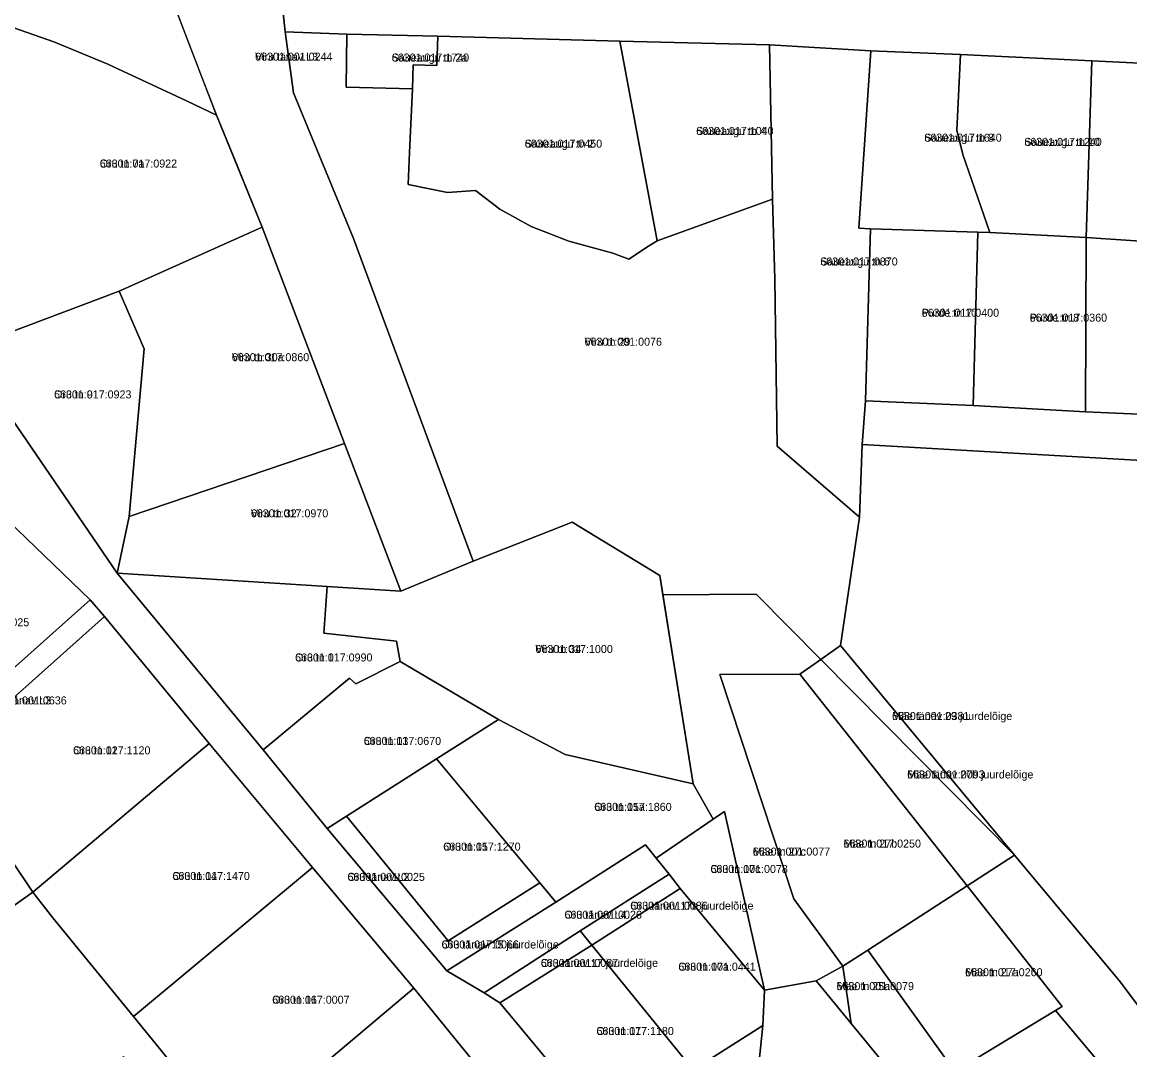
# Model space of a CAD drawing. Extents: x 632278 to 636344, y 6578401 to 6583362.
# Drawn here: x 634575.5 to 634783.1, y 6579911.1 to 6580103.6 of the extents above; entities that cross this region are included whole.
import ezdxf

# ---------------------------------------------------------------- set-up
doc = ezdxf.new("R2010")
doc.units = 0
for name, color, linetype in [('L_AADRESS', 7, 'Continuous'), ('PIIR', 7, 'Continuous'), ('TUNNUS', 7, 'Continuous')]:
    doc.layers.add(name, color=color, linetype=linetype)

msp = doc.modelspace()

# ---------------------------------------------------------------- linework, layer by layer
at = {"layer": 'PIIR'}
for points in [[(634596.17, 6580180.31), (634593.18, 6580175.41), (634611.72, 6580129.48), (634622.67, 6580121.96), (634624.79, 6580101.82), (634626.34, 6580090.38), (634637.59, 6580063.12), (634659.99, 6580002.69), (634646.47, 6579997.05), (634635.9, 6580024.72), (634620.47, 6580065.25), (634611.9, 6580086.21), (634578.31, 6580173.81)], [(634561.45, 6580109.75), (634542.88, 6580160.31), (634578.31, 6580173.81), (634609.25, 6580093.13), (634611.9, 6580086.21), (634606.27, 6580088.9), (634591.53, 6580095.77), (634581.47, 6580099.94), (634562.64, 6580106.5)], [(634556.42, 6580103.56), (634555.32, 6580107.46), (634562.64, 6580106.5), (634581.47, 6580099.94), (634591.53, 6580095.77), (634606.27, 6580088.9), (634611.9, 6580086.21), (634615.1, 6580078.5), (634620.47, 6580065.25), (634593.68, 6580053.25), (634572.83, 6580045.36), (634570.36, 6580054.45)], [(634637.59, 6580063.12), (634626.34, 6580090.38), (634624.79, 6580101.82), (634636.33, 6580101.4), (634636.21, 6580091.45), (634648.62, 6580091.14), (634648.09, 6580079.23), (634647.83, 6580073.21), (634655.2, 6580071.74), (634660.42, 6580072.09), (634664.98, 6580068.62), (634670.89, 6580065.34), (634677.94, 6580062.63), (634686.21, 6580060.39), (634689.19, 6580059.24), (634692.85, 6580061.68), (634694.48, 6580062.67), (634716.08, 6580070.46), (634716.54, 6580055.5), (634716.98, 6580024.24), (634732.38, 6580010.94), (634728.84, 6579986.89), (634725.15, 6579984.23), (634713.06, 6579996.48), (634695.55, 6579996.39), (634694.97, 6580000.01), (634678.59, 6580009.97), (634659.99, 6580002.69)], [(634636.33, 6580101.4), (634653.37, 6580101.04), (634653.22, 6580095.54), (634648.78, 6580095.63), (634648.62, 6580091.14), (634636.21, 6580091.45)], [(634655.2, 6580071.74), (634647.83, 6580073.21), (634648.09, 6580079.23), (634648.62, 6580091.14), (634648.78, 6580095.63), (634653.22, 6580095.54), (634653.37, 6580101.04), (634687.52, 6580100.1), (634694.48, 6580062.67), (634692.85, 6580061.68), (634689.19, 6580059.24), (634686.21, 6580060.39), (634677.94, 6580062.63), (634670.89, 6580065.34), (634664.98, 6580068.62), (634660.42, 6580072.09)], [(634687.52, 6580100.1), (634715.56, 6580099.38), (634716.08, 6580070.46), (634694.48, 6580062.67)], [(634716.54, 6580055.5), (634716.08, 6580070.46), (634715.56, 6580099.38), (634734.54, 6580098.3), (634732.28, 6580065.04), (634734.48, 6580064.95), (634733.53, 6580032.72), (634732.89, 6580024.54), (634732.38, 6580010.94), (634716.98, 6580024.24)], [(634732.28, 6580065.04), (634734.54, 6580098.3), (634751.34, 6580097.62), (634750.64, 6580083.43), (634751.77, 6580078.84), (634756.79, 6580064.23), (634754.57, 6580064.3), (634734.48, 6580064.95)], [(634751.77, 6580078.84), (634750.64, 6580083.43), (634751.34, 6580097.62), (634775.92, 6580096.43), (634774.87, 6580063.32), (634756.79, 6580064.23)], [(634775.92, 6580096.43), (634796.5, 6580095.39), (634795.24, 6580061.94), (634774.87, 6580063.32)], [(634635.9, 6580024.72), (634595.56, 6580011.04), (634598.34, 6580042.43), (634593.68, 6580053.25), (634620.47, 6580065.25)], [(634734.48, 6580064.95), (634754.57, 6580064.3), (634753.7, 6580031.86), (634733.53, 6580032.72)], [(634753.7, 6580031.86), (634754.57, 6580064.3), (634756.79, 6580064.23), (634774.87, 6580063.32), (634774.77, 6580030.62)], [(634774.87, 6580063.32), (634795.24, 6580061.94), (634795.1, 6580059.7), (634794.75, 6580029.74), (634774.77, 6580030.62)], [(634564.61, 6580042.35), (634572.83, 6580045.36), (634593.68, 6580053.25), (634598.34, 6580042.43), (634595.56, 6580011.04), (634593.28, 6580000.44)], [(634732.89, 6580024.54), (634733.53, 6580032.72), (634753.7, 6580031.86), (634774.77, 6580030.62), (634794.75, 6580029.74), (634814.69, 6580028.75), (634851.2, 6580027.06), (634854.12, 6580028.32), (634856.31, 6580031.16), (634861.77, 6580022.17), (634829.01, 6580019.04)], [(634595.56, 6580011.04), (634635.9, 6580024.72), (634646.47, 6579997.05), (634632.65, 6579997.94), (634593.28, 6580000.44)], [(634732.89, 6580024.54), (634829.01, 6580019.04), (634843.75, 6579980.63), (634826.43, 6579969), (634849.45, 6579936.6), (634838.42, 6579929.05), (634798.01, 6579901.48), (634781.03, 6579924.08), (634761.47, 6579947.6), (634728.84, 6579986.89), (634732.38, 6580010.94)], [(634568.5, 6580013.07), (634569.33, 6580013.61), (634588.26, 6579995.4), (634556.7, 6579967.34), (634534.91, 6580001.49), (634557.34, 6580004.98)], [(634646.32, 6579983.88), (634645.66, 6579987.66), (634632, 6579989.21), (634632.65, 6579997.94), (634646.47, 6579997.05), (634659.99, 6580002.69), (634678.59, 6580009.97), (634694.97, 6580000.01), (634701.21, 6579960.94), (634677.22, 6579966.46), (634664.75, 6579973.02)], [(634632.65, 6579997.94), (634632, 6579989.21), (634645.66, 6579987.66), (634646.32, 6579983.88), (634638.01, 6579979.71), (634636.87, 6579980.72), (634620.65, 6579967.31), (634593.28, 6580000.44)], [(634529.32, 6579956.26), (634528.51, 6579960.39), (634556.7, 6579967.34), (634588.26, 6579995.4), (634590.91, 6579992.32), (634560.81, 6579965.44), (634557.24, 6579963.18)], [(634701.21, 6579960.94), (634695.55, 6579996.39), (634713.06, 6579996.48), (634725.15, 6579984.23), (634721.22, 6579981.5), (634706.26, 6579981.43), (634720.12, 6579939.4), (634729.25, 6579926.79), (634724.25, 6579924.06), (634714.62, 6579922.27), (634707.13, 6579955.8), (634704.99, 6579954.34)], [(634577.5, 6579940.63), (634560.81, 6579965.44), (634590.91, 6579992.32), (634610.54, 6579968.53)], [(634728.84, 6579986.89), (634761.47, 6579947.6), (634725.15, 6579984.23)], [(634620.65, 6579967.31), (634636.87, 6579980.72), (634638.01, 6579979.71), (634646.32, 6579983.88), (634664.75, 6579973.02), (634653.17, 6579965.66), (634636.3, 6579954.91), (634632.67, 6579952.59)], [(634752.56, 6579941.83), (634721.22, 6579981.5), (634725.15, 6579984.23), (634761.47, 6579947.6)], [(634720.12, 6579939.4), (634706.26, 6579981.43), (634721.22, 6579981.5), (634752.56, 6579941.83), (634733.98, 6579929.82), (634729.25, 6579926.79)], [(634672.51, 6579942.41), (634653.17, 6579965.66), (634664.75, 6579973.02), (634677.22, 6579966.46), (634701.21, 6579960.94), (634704.99, 6579954.34), (634694.32, 6579947.04), (634692.33, 6579949.53), (634675.49, 6579938.76)], [(634581.24, 6579935.83), (634577.5, 6579940.63), (634610.54, 6579968.53), (634629.9, 6579945.27), (634596.35, 6579917.35)], [(634533.05, 6579938.89), (634529.32, 6579956.26), (634557.24, 6579963.18), (634560.81, 6579965.44), (634577.5, 6579940.63), (634556.45, 6579925.73), (634554.62, 6579929.91), (634548.8, 6579942.83)], [(634672.51, 6579942.41), (634655.34, 6579931.55), (634636.3, 6579954.91), (634653.17, 6579965.66)], [(634698.8, 6579941.36), (634696.74, 6579944.03), (634694.32, 6579947.04), (634704.99, 6579954.34), (634707.13, 6579955.8), (634714.62, 6579922.27), (634713.35, 6579923.81)], [(634632.67, 6579952.59), (634636.3, 6579954.91), (634655.34, 6579931.55), (634672.51, 6579942.41), (634675.49, 6579938.76), (634655.09, 6579925.92)], [(634662.07, 6579921.82), (634655.09, 6579925.92), (634675.52, 6579938.78), (634692.33, 6579949.53), (634694.32, 6579947.04), (634696.74, 6579944.03), (634680.08, 6579933.39)], [(634596.35, 6579917.35), (634629.9, 6579945.27), (634648.9, 6579922.66), (634615.16, 6579894.25)], [(634682.27, 6579930.7), (634680.08, 6579933.39), (634696.74, 6579944.03), (634698.8, 6579941.36)], [(634682.27, 6579930.7), (634698.8, 6579941.36), (634713.35, 6579923.81), (634714.62, 6579922.27), (634714.27, 6579915.65), (634712.52, 6579914.54), (634701.22, 6579907.36)], [(634769.15, 6579918.49), (634752.02, 6579908.13), (634750.26, 6579907.07), (634733.98, 6579929.82), (634752.56, 6579941.83), (634770.4, 6579919.25)], [(634570.22, 6579894.2), (634556.45, 6579925.73), (634577.5, 6579940.63), (634581.24, 6579935.83), (634596.35, 6579917.35), (634615.16, 6579894.25), (634628.49, 6579878.01), (634623.25, 6579874.72), (634594.58, 6579909.83)], [(634664.99, 6579919.9), (634662.07, 6579921.82), (634680.08, 6579933.39), (634682.27, 6579930.7)], [(634682.27, 6579930.7), (634701.22, 6579907.36), (634684.34, 6579896.64), (634664.99, 6579919.9)], [(634740.03, 6579904.85), (634730.81, 6579916.04), (634729.25, 6579926.79), (634733.98, 6579929.82), (634750.26, 6579907.07), (634752.02, 6579908.13), (634771.69, 6579884.62), (634754.9, 6579873.86), (634733.36, 6579899.72)], [(634724.25, 6579924.06), (634729.25, 6579926.79), (634730.81, 6579916.04)], [(634628.49, 6579878.01), (634615.16, 6579894.25), (634648.9, 6579922.66), (634665.82, 6579901.86)], [(634738.01, 6579863.17), (634718.71, 6579886.44), (634717.38, 6579888.19), (634713.63, 6579908.98), (634714.27, 6579915.65), (634714.62, 6579922.27), (634724.25, 6579924.06), (634730.81, 6579916.04), (634740.03, 6579904.85), (634733.36, 6579899.72), (634754.9, 6579873.86)], [(634769.15, 6579918.49), (634788.63, 6579895.28), (634771.69, 6579884.62), (634752.02, 6579908.13)], [(634703.24, 6579904.94), (634701.22, 6579907.36), (634712.52, 6579914.54), (634714.27, 6579915.65), (634713.63, 6579908.98), (634707.56, 6579899.77)]]:
    msp.add_lwpolyline(points, close=True, dxfattribs=at)
for points in [[(634796.5, 6580095.39), (634775.92, 6580096.43), (634751.34, 6580097.62), (634734.54, 6580098.3), (634715.56, 6580099.38), (634687.52, 6580100.1), (634653.37, 6580101.04), (634636.33, 6580101.4), (634624.79, 6580101.82), (634622.67, 6580121.96), (634632.9, 6580114.93), (634638.48, 6580114.65), (634663.24, 6580113.39), (634693.56, 6580111.9), (634703.37, 6580111.31), (634728.83, 6580110.06), (634758.51, 6580108.49), (634765.46, 6580108.24), (634785.89, 6580107.22)], [(634665.82, 6579901.86), (634648.9, 6579922.66), (634629.9, 6579945.27), (634610.54, 6579968.53), (634590.91, 6579992.32), (634588.26, 6579995.4), (634569.33, 6580013.61), (634568.5, 6580013.07), (634558.03, 6580028.45), (634551.85, 6580037.89), (634564.61, 6580042.35), (634593.28, 6580000.44), (634620.65, 6579967.31), (634632.67, 6579952.59), (634655.09, 6579925.92), (634662.07, 6579921.82), (634664.99, 6579919.9), (634684.34, 6579896.64)], [(634788.63, 6579895.28), (634769.15, 6579918.49), (634770.4, 6579919.25), (634752.56, 6579941.83), (634761.47, 6579947.6), (634781.03, 6579924.08), (634798.01, 6579901.48), (634838.42, 6579929.05), (634840.49, 6579911.35), (634827.14, 6579901.97)]]:
    msp.add_lwpolyline(points, dxfattribs=at)

# ---------------------------------------------------------------- texts
at = {"layer": 'L_AADRESS'}
for s, p in [('Viru tänav L3', (634619.15, 6580096.43)), ('Saueaugu tn 2a', (634644.75, 6580096.27)), ('Saueaugu tn 4', (634701.8, 6580082.52)), ('Saueaugu tn 8', (634744.54, 6580081.26)), ('Saueaugu tn 2', (634669.68, 6580080.14)), ('Saueaugu tn 10', (634763.28, 6580080.47)), ('Oru tn 7a', (634590.04, 6580076.41)), ('Saueaugu tn 6', (634725.05, 6580058.06)), ('Purde tn 10', (634744.05, 6580048.46)), ('Purde tn 8', (634764.29, 6580047.54)), ('Viru tn 29', (634680.88, 6580043.03)), ('Viru tn 30a', (634614.79, 6580040.13)), ('Oru tn 9', (634581.48, 6580033.16)), ('Viru tn 32', (634618.36, 6580010.88)), ('Viru tn 34', (634671.67, 6579985.46)), ('Oru tn 11', (634626.64, 6579983.88)), ('Oru tänav L3', (634569.35, 6579975.83)), ('Mäe tänav 29 juurdelõige', (634738.49, 6579972.91)), ('Oru tn 12', (634585.04, 6579966.48)), ('Oru tn 13', (634639.5, 6579968.24)), ('Mäe tänav 27b juurdelõige', (634741.34, 6579961.96)), ('Oru tn 15a', (634682.7, 6579955.89)), ('Oru tn 15', (634654.4, 6579948.44)), ('Mäe tn 27b', (634729.41, 6579949.01)), ('Mäe tn 27c', (634712.4, 6579947.51)), ('Oru tn 17c', (634704.47, 6579944.25)), ('Oru tn 14', (634603.67, 6579942.94)), ('Oru tänav L2', (634636.46, 6579942.77)), ('Oru tänav 17a juurdelõige', (634689.45, 6579937.37)), ('Oru tänav L4', (634677.12, 6579935.68)), ('Oru tänav 15 juurdelõige', (634654.08, 6579930.11)), ('Oru tänav 17 juurdelõige', (634672.68, 6579926.65)), ('Oru tn 17a', (634698.45, 6579925.95)), ('Mäe tn 27a', (634752.19, 6579924.91)), ('Mäe tn 25a', (634728.1, 6579922.3)), ('Oru tn 16', (634622.35, 6579919.76)), ('Oru tn 17', (634683.11, 6579913.9))]:
    msp.add_text(s, height=1.5, dxfattribs=at).set_placement(p)
at = {"layer": 'TUNNUS'}
for s, p in [('66301:001:0244', (634619.15, 6580096.43)), ('66301:017:1740', (634644.75, 6580096.27)), ('66301:017:1040', (634701.8, 6580082.52)), ('66301:017:1640', (634744.54, 6580081.26)), ('66301:017:0450', (634669.68, 6580080.14)), ('66301:017:1240', (634763.28, 6580080.47)), ('66301:017:0922', (634590.04, 6580076.41)), ('66301:017:0870', (634725.05, 6580058.06)), ('66301:017:0400', (634744.05, 6580048.46)), ('66301:017:0360', (634764.29, 6580047.54)), ('66301:001:0076', (634680.88, 6580043.03)), ('66301:017:0860', (634614.79, 6580040.13)), ('66301:017:0923', (634581.48, 6580033.16)), ('66301:017:0970', (634618.36, 6580010.88)), ('66301:017:0025', (634562.33, 6579990.48)), ('66301:017:1000', (634671.67, 6579985.46)), ('66301:017:0990', (634626.64, 6579983.88)), ('66301:001:0636', (634569.35, 6579975.83)), ('66301:001:0381', (634738.49, 6579972.91)), ('66301:017:1120', (634585.04, 6579966.48)), ('66301:017:0670', (634639.5, 6579968.24)), ('66301:001:0093', (634741.34, 6579961.96)), ('66301:017:1860', (634682.7, 6579955.89)), ('66301:017:1270', (634654.4, 6579948.44)), ('66301:017:0250', (634729.41, 6579949.01)), ('66301:001:0077', (634712.4, 6579947.51)), ('66301:001:0078', (634704.47, 6579944.25)), ('66301:017:1470', (634603.67, 6579942.94)), ('66301:001:0025', (634636.46, 6579942.77)), ('66301:001:0086', (634689.45, 6579937.37)), ('66301:001:0026', (634677.12, 6579935.68)), ('66301:017:0066', (634654.08, 6579930.11)), ('66301:001:0087', (634672.68, 6579926.65)), ('66301:001:0441', (634698.45, 6579925.95)), ('66301:017:0260', (634752.19, 6579924.91)), ('66301:001:0079', (634728.1, 6579922.3)), ('66301:017:0007', (634622.35, 6579919.76)), ('66301:017:1180', (634683.11, 6579913.9))]:
    msp.add_text(s, height=1.5, dxfattribs=at).set_placement(p)

doc.saveas('drawing.dxf')
